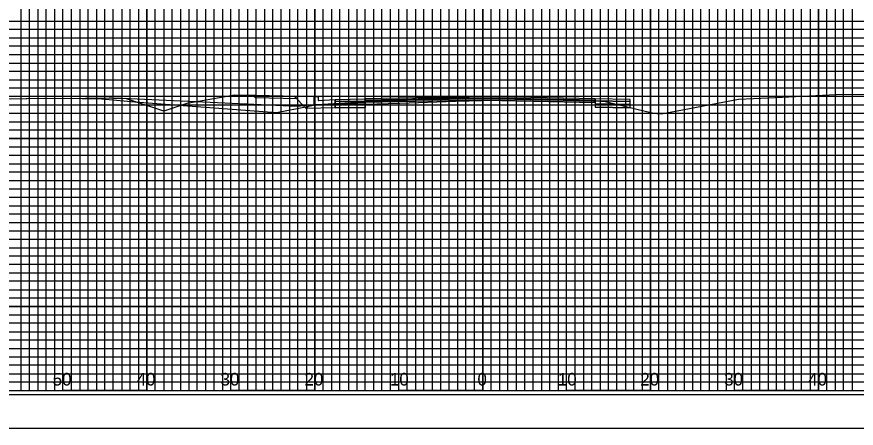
# Model space of a CAD drawing. Extents: x -13 to 760, y -5 to 1491.
# Drawn here: x 104.5 to 204.5, y 314.5 to 363.5 of the extents above; entities that cross this region are included whole.
import ezdxf

# ---------------------------------------------------------------- set-up
doc = ezdxf.new("R2010")
doc.units = 0
for name, color, linetype in [('Exist XS Ground Line', 7, 'Continuous'), ('Prop CMT Pvmt Course 1', 7, 'Continuous'), ('Prop CMT Pvmt Course 2', 7, 'Continuous'), ('Prop CMT Pvmt Course 3', 7, 'Continuous'), ('Prop CMT Subgrade Earthwork', 7, 'Continuous'), ('Prop Conc 4in Sidewalk', 7, 'Continuous'), ('Prop Conc Curb and Gutter', 7, 'Continuous'), ('Prop Conc Island Cover', 7, 'Continuous'), ('Prop Corridor Mesh Bottom', 7, 'Continuous'), ('Prop XS Alignment Label', 7, 'Continuous'), ('Prop XS Finish Grade', 7, 'Continuous'), ('Prop XS Offset Labels', 7, 'Continuous'), ('Scratch_Level_9', 7, 'Continuous'), ('Sheet Cross Section CELL', 7, 'Continuous'), ('Sheet Cross Section Grid Major CELL', 7, 'Continuous'), ('Sheet Cross Section Grid Middle CELL', 7, 'Continuous'), ('Sheet Cross Section Grid Minor 1 CELL', 7, 'Continuous'), ('Sheet Cross Section Grid Minor 2 CELL', 7, 'Continuous'), ('Sheet Cutting Line CELL', 7, 'Continuous'), ('Sheet DOT Grid CELL', 7, 'Continuous'), ('Sheet Plot Border Inside CELL', 7, 'Continuous'), ('Sheet Plot Border Outside CELL', 7, 'Continuous')]:
    doc.layers.add(name, color=color, linetype=linetype)

msp = doc.modelspace()

# ---------------------------------------------------------------- linework, layer by layer
at = {"layer": 'Exist XS Ground Line'}
for points in [[(91.42, 353.71), (112.67, 353.83), (115.52, 353.84), (115.73, 353.84), (115.82, 353.84), (116.11, 353.83), (117.11, 353.8), (137.99, 352.86), (139.25, 353), (150.14, 353.54), (156.76, 353.88), (162.26, 353.74), (173.76, 353.51), (173.95, 353.45), (174.43, 353.47), (179.37, 352.25), (180.23, 352.08), (180.73, 351.98), (181.44, 351.98), (181.49, 351.98), (183.17, 352.29), (185.26, 352.69), (190.46, 353.69), (194.06, 353.87), (202.9, 354.27), (210.32, 354.23)], [(103.75, 353.73), (105.7, 353.77), (107.85, 353.81), (112.3, 353.79), (114.65, 353.73), (118.99, 353.35), (119.15, 353.34), (120.15, 353.25), (124.34, 352.92), (135.44, 352.12), (137.89, 352.59), (140.25, 353.05), (149.62, 353.62), (152.32, 353.79), (153.61, 353.81), (158.33, 353.86), (159.93, 353.85), (163.2, 353.81), (167.05, 353.69), (174.43, 353.47), (179.37, 352.25), (180.23, 352.08), (180.73, 351.98), (181.44, 351.98), (181.49, 351.98), (183.17, 352.29), (185.26, 352.69), (190.46, 353.69), (194.06, 353.87), (202.9, 354.27), (210.32, 354.23)]]:
    msp.add_lwpolyline(points, dxfattribs=at)
at = {"layer": 'Prop CMT Pvmt Course 1'}
for points in [[(146, 353.56), (146, 353.56), (146, 353.56), (160, 353.84), (160, 353.84), (173.4, 353.57), (173.4, 353.57), (173.4, 353.74), (160, 354), (160, 354), (146, 353.72), (146, 353.72), (146, 353.56)], [(142.41, 353.65), (146, 353.72), (146, 353.47), (146, 353.47), (142.41, 353.4), (142.41, 353.4), (142.41, 353.4), (142.41, 353.65), (142.41, 353.65)], [(177.59, 353.65), (173.4, 353.74), (173.4, 353.49), (173.4, 353.49), (177.59, 353.4), (177.59, 353.4), (177.59, 353.4), (177.59, 353.65), (177.59, 353.65)]]:
    msp.add_lwpolyline(points, dxfattribs=at)
at = {"layer": 'Prop CMT Pvmt Course 2'}
for points in [[(142.41, 353.4), (146, 353.47), (146, 353.14), (146, 353.14), (142.41, 353.07), (142.41, 353.07), (142.41, 353.07), (142.41, 353.4), (142.41, 353.4)], [(146, 353.5), (146, 353.5), (146, 353.5), (160, 353.78), (160, 353.78), (173.4, 353.51), (173.4, 353.51), (173.4, 353.57), (160, 353.84), (160, 353.84), (146, 353.56), (146, 353.56), (146, 353.5)], [(177.59, 353.4), (173.4, 353.49), (173.4, 353.15), (173.4, 353.15), (177.59, 353.07), (177.59, 353.07), (177.59, 353.07), (177.59, 353.4), (177.59, 353.4)]]:
    msp.add_lwpolyline(points, dxfattribs=at)
at = {"layer": 'Prop CMT Pvmt Course 3'}
for points in [[(142.41, 353.07), (142.41, 352.65), (138.99, 352.58), (139.41, 353.01), (142.41, 353.07)], [(142.41, 353.07), (146, 353.14), (146, 352.72), (146, 352.72), (142.41, 352.65), (142.41, 352.65), (142.41, 352.65), (142.41, 353.07), (142.41, 353.07)], [(146, 353.33), (146, 353.33), (146, 353.33), (160, 353.61), (160, 353.61), (173.4, 353.34), (173.4, 353.34), (173.4, 353.51), (160, 353.78), (160, 353.78), (146, 353.5), (146, 353.5), (146, 353.33)], [(177.59, 353.07), (173.4, 353.15), (173.4, 352.74), (173.4, 352.74), (177.59, 352.65), (177.59, 352.65), (177.59, 352.65), (177.59, 353.07), (177.59, 353.07)]]:
    msp.add_lwpolyline(points, dxfattribs=at)
at = {"layer": 'Prop CMT Subgrade Earthwork'}
for points in [[(138.99, 352.58), (137.49, 354.08)], [(142.41, 352.65), (138.99, 352.58)], [(142.41, 352.65), (142.41, 352.65), (146, 352.72)], [(177.59, 352.65), (177.59, 352.65), (173.4, 352.74)]]:
    msp.add_lwpolyline(points, dxfattribs=at)
at = {"layer": 'Prop Conc 4in Sidewalk'}
msp.add_lwpolyline([(137.91, 354.07), (137.92, 353.74), (132.9, 353.84), (132.91, 354.17), (137.91, 354.07)], dxfattribs=at)
at = {"layer": 'Prop Conc Curb and Gutter'}
msp.add_lwpolyline([(140.46, 353.53), (142.41, 353.65), (142.41, 353.07), (142.41, 353.07), (139.99, 353.02), (139.91, 353.02), (139.91, 353.05), (139.91, 354.03), (140.4, 354.03), (140.41, 354.03), (140.41, 353.54), (140.41, 353.53), (140.46, 353.53)], dxfattribs=at)
at = {"layer": 'Prop Conc Island Cover'}
msp.add_lwpolyline([(125, 353.25), (129.56, 354.06), (130.41, 354.22), (132.61, 354.17), (132.91, 354.17)], dxfattribs=at)
at = {"layer": 'Prop Corridor Mesh Bottom'}
for points in [[(122, 352.25), (117.46, 353.76)], [(125, 353.25), (122, 352.25)], [(156.76, 353.88), (150.14, 353.54), (150.14, 353.54), (146, 353.33), (146, 353.08), (146, 353.08), (150.14, 353.22), (150.14, 353.22), (156.76, 353.44), (156.76, 353.44), (160, 353.55), (160, 353.55), (160, 353.8), (156.76, 353.88), (156.76, 353.88)], [(173.4, 353.52), (173.4, 353.52), (173.4, 353.27), (173.4, 353.27), (173.4, 353.27), (162.26, 353.5), (162.26, 353.5), (160, 353.55), (160, 353.55), (160, 353.8), (162.26, 353.74), (162.26, 353.74), (173.4, 353.52)]]:
    msp.add_lwpolyline(points, dxfattribs=at)
at = {"layer": 'Prop XS Finish Grade'}
msp.add_lwpolyline([(137.91, 354.07), (139.85, 354.03), (139.91, 354.03)], dxfattribs=at)
at = {"layer": 'Scratch_Level_9'}
msp.add_lwpolyline([(142.41, 353.65), (142.41, 353.4)], dxfattribs=at)
at = {"layer": 'Sheet Cross Section CELL'}
msp.add_lwpolyline([(320, 529), (0, 529), (0, 319), (320, 319)], close=True, dxfattribs=at)
at = {"layer": 'Sheet Cross Section Grid Major CELL'}
for p, q in [((110, 319), (110, 529)), ((120, 529), (120, 319)), ((130, 319), (130, 529)), ((140, 529), (140, 319)), ((150, 319), (150, 529)), ((160, 529), (160, 319)), ((170, 319), (170, 529)), ((180, 529), (180, 319)), ((190, 319), (190, 529)), ((200, 529), (200, 319)), ((120, 319), (110, 319)), ((140, 319), (130, 319)), ((160, 319), (150, 319)), ((180, 319), (170, 319)), ((200, 319), (190, 319))]:
    msp.add_line(p, q, dxfattribs=at)
for points in [[(0, 359), (320, 359), (320, 349), (0, 349)], [(0, 339), (320, 339), (320, 329), (0, 329)]]:
    msp.add_lwpolyline(points, dxfattribs=at)
at = {"layer": 'Sheet Cross Section Grid Middle CELL'}
for points in [[(105, 529), (105, 319), (115, 319), (115, 529)], [(125, 529), (125, 319), (135, 319), (135, 529)], [(145, 529), (145, 319), (155, 319), (155, 529)], [(165, 529), (165, 319), (175, 319), (175, 529)], [(185, 529), (185, 319), (195, 319), (195, 529)], [(0, 344), (320, 344), (320, 354), (0, 354)], [(0, 324), (320, 324), (320, 334), (0, 334)]]:
    msp.add_lwpolyline(points, dxfattribs=at)
at = {"layer": 'Sheet Cross Section Grid Minor 1 CELL'}
for points in [[(0, 363), (320, 363), (320, 362), (0, 362)], [(0, 361), (320, 361), (320, 360), (0, 360)], [(0, 358), (320, 358), (320, 357), (0, 357)], [(0, 356), (320, 356), (320, 355), (0, 355)], [(0, 353), (320, 353), (320, 352), (0, 352)], [(0, 351), (320, 351), (320, 350), (0, 350)], [(0, 348), (320, 348), (320, 347), (0, 347)], [(0, 346), (320, 346), (320, 345), (0, 345)], [(0, 343), (320, 343), (320, 342), (0, 342)], [(0, 341), (320, 341), (320, 340), (0, 340)], [(0, 338), (320, 338), (320, 337), (0, 337)], [(0, 336), (320, 336), (320, 335), (0, 335)], [(0, 333), (320, 333), (320, 332), (0, 332)], [(0, 331), (320, 331), (320, 330), (0, 330)], [(0, 328), (320, 328), (320, 327), (0, 327)], [(0, 326), (320, 326), (320, 325), (0, 325)], [(0, 323), (320, 323), (320, 322), (0, 322)], [(0, 321), (320, 321), (320, 320), (0, 320)]]:
    msp.add_lwpolyline(points, dxfattribs=at)
at = {"layer": 'Sheet Cross Section Grid Minor 2 CELL'}
for points in [[(105, 319), (106, 319), (106, 529), (107, 529), (107, 319)], [(107, 319), (108, 319), (108, 529), (109, 529), (109, 319)], [(110, 319), (111, 319), (111, 529), (112, 529), (112, 319)], [(112, 319), (113, 319), (113, 529), (114, 529), (114, 319)], [(115, 319), (116, 319), (116, 529), (117, 529), (117, 319)], [(117, 319), (118, 319), (118, 529), (119, 529), (119, 319)], [(120, 319), (121, 319), (121, 529), (122, 529), (122, 319)], [(122, 319), (123, 319), (123, 529), (124, 529), (124, 319)], [(125, 319), (126, 319), (126, 529), (127, 529), (127, 319)], [(127, 319), (128, 319), (128, 529), (129, 529), (129, 319)], [(130, 319), (131, 319), (131, 529), (132, 529), (132, 319)], [(132, 319), (133, 319), (133, 529), (134, 529), (134, 319)], [(135, 319), (136, 319), (136, 529), (137, 529), (137, 319)], [(137, 319), (138, 319), (138, 529), (139, 529), (139, 319)], [(140, 319), (141, 319), (141, 529), (142, 529), (142, 319)], [(142, 319), (143, 319), (143, 529), (144, 529), (144, 319)], [(145, 319), (146, 319), (146, 529), (147, 529), (147, 319)], [(147, 319), (148, 319), (148, 529), (149, 529), (149, 319)], [(150, 319), (151, 319), (151, 529), (152, 529), (152, 319)], [(152, 319), (153, 319), (153, 529), (154, 529), (154, 319)], [(155, 319), (156, 319), (156, 529), (157, 529), (157, 319)], [(157, 319), (158, 319), (158, 529), (159, 529), (159, 319)], [(160, 319), (161, 319), (161, 529), (162, 529), (162, 319)], [(162, 319), (163, 319), (163, 529), (164, 529), (164, 319)], [(165, 319), (166, 319), (166, 529), (167, 529), (167, 319)], [(167, 319), (168, 319), (168, 529), (169, 529), (169, 319)], [(170, 319), (171, 319), (171, 529), (172, 529), (172, 319)], [(172, 319), (173, 319), (173, 529), (174, 529), (174, 319)], [(175, 319), (176, 319), (176, 529), (177, 529), (177, 319)], [(177, 319), (178, 319), (178, 529), (179, 529), (179, 319)], [(180, 319), (181, 319), (181, 529), (182, 529), (182, 319)], [(182, 319), (183, 319), (183, 529), (184, 529), (184, 319)], [(185, 319), (186, 319), (186, 529), (187, 529), (187, 319)], [(187, 319), (188, 319), (188, 529), (189, 529), (189, 319)], [(190, 319), (191, 319), (191, 529), (192, 529), (192, 319)], [(192, 319), (193, 319), (193, 529), (194, 529), (194, 319)], [(195, 319), (196, 319), (196, 529), (197, 529), (197, 319)], [(197, 319), (198, 319), (198, 529), (199, 529), (199, 319)], [(200, 319), (201, 319), (201, 529), (202, 529), (202, 319)], [(202, 319), (203, 319), (203, 529), (204, 529), (204, 319)]]:
    msp.add_lwpolyline(points, dxfattribs=at)
at = {"layer": 'Sheet Cutting Line CELL'}
msp.add_line((-13.4, 314.5), (323.3, 314.5), dxfattribs=at)
at = {"layer": 'Sheet DOT Grid CELL'}
for p, q in [((110, 319), (110, 529)), ((120, 319), (120, 529)), ((130, 319), (130, 529)), ((140, 319), (140, 529)), ((150, 319), (150, 529)), ((160, 319), (160, 529)), ((170, 319), (170, 529)), ((180, 319), (180, 529)), ((190, 319), (190, 529)), ((200, 319), (200, 529)), ((0, 359), (320, 359)), ((0, 349), (320, 349)), ((0, 339), (320, 339)), ((0, 329), (320, 329))]:
    msp.add_line(p, q, dxfattribs=at)
at = {"layer": 'Sheet Plot Border Inside CELL'}
msp.add_lwpolyline([(-10.8, 318.5), (322.4, 318.5), (322.4, 529.5), (-10.8, 529.5)], close=True, dxfattribs=at)
at = {"layer": 'Sheet Plot Border Outside CELL'}
msp.add_lwpolyline([(-13.4, 314.5), (323.3, 314.5), (323.3, 533.5), (-13.4, 533.5)], close=True, dxfattribs=at)

# ---------------------------------------------------------------- texts
at = {"layer": 'Prop XS Alignment Label'}
msp.add_text('.', height=0.01, dxfattribs=at).set_placement((160.27, 324.33))
at = {"layer": 'Prop XS Offset Labels'}
for s, p in [('50', (108.78, 319.59)), ('40', (118.78, 319.59)), ('30', (128.78, 319.59)), ('20', (138.78, 319.59)), ('10', (148.96, 319.59)), ('0', (159.38, 319.59)), ('0', (159.38, 319.59)), ('10', (168.96, 319.59)), ('20', (178.78, 319.59)), ('30', (188.78, 319.59)), ('40', (198.78, 319.59))]:
    msp.add_text(s, height=1.5, dxfattribs=at).set_placement(p)
at = {"layer": 'Scratch_Level_9'}
for p in [(132.91, 354.17), (137.91, 354.07), (160, 354), (117.46, 353.76), (140.41, 353.53), (142.41, 353.65), (142.41, 353.65), (177.58, 353.65)]:
    msp.add_text('X', height=0.0025, dxfattribs=at).set_placement(p)

doc.saveas('drawing.dxf')
